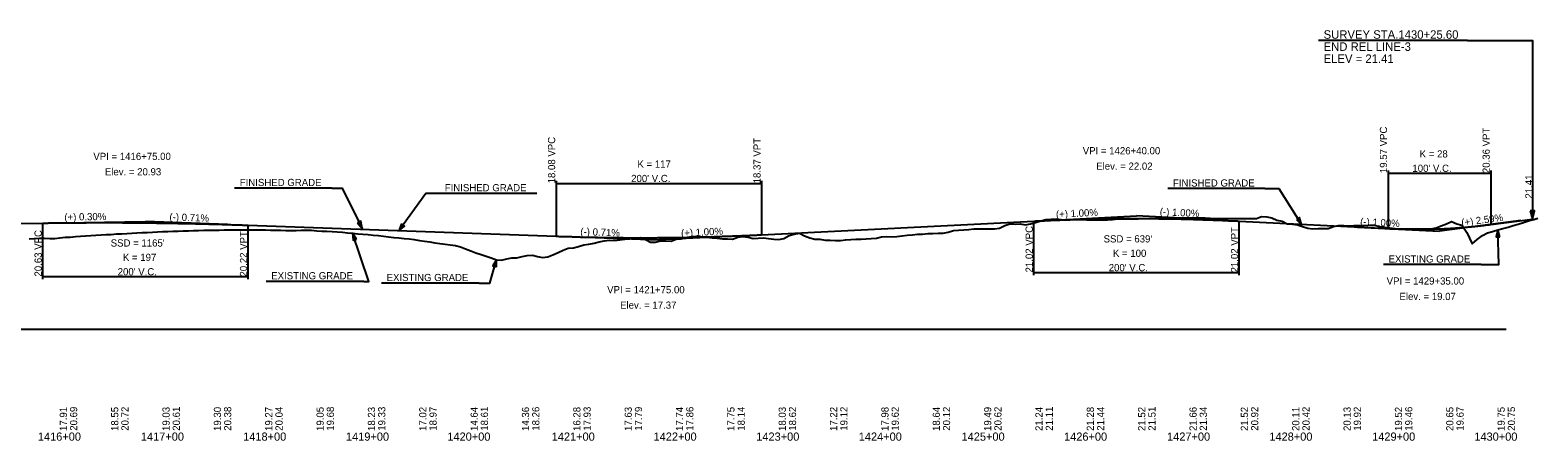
# Model space of a CAD drawing. Extents: x 2360994 to 2383826, y 330623 to 403123.
# Drawn here: x 2373088 to 2374556, y 351764 to 352164 of the extents above; entities that cross this region are included whole.
import ezdxf

# ---------------------------------------------------------------- set-up
doc = ezdxf.new("R2010")
doc.units = 0
for name, color, linetype in [('RD_DDB_GradeTX', 7, 'Continuous'), ('RD_DDB_Profile_EX', 7, 'Continuous'), ('RD_DDB_Profile_Lbl', 7, 'Continuous'), ('RD_DDB_Profile_PR', 7, 'Continuous'), ('RD_DDB_StaTX', 7, 'Continuous'), ('RD_DDB_StripGrade', 7, 'Continuous'), ('RD_DDB_VCLbl', 7, 'Continuous'), ('RD_GPK_Profile_Cell', 7, 'Continuous'), ('RD_TX_Profile', 7, 'Continuous')]:
    doc.layers.add(name, color=color, linetype=linetype)

msp = doc.modelspace()

# ---------------------------------------------------------------- linework, layer by layer
at = {"layer": 'RD_DDB_GradeTX'}
for p, q in [((2373120.6, 351976.3), (2373200.6, 351977.5)), ((2373280.5, 351974.7), (2373200.6, 351977.5)), ((2374085.7, 351979), (2374165.6, 351983)), ((2374245.5, 351979), (2374165.6, 351983)), ((2374380.7, 351972.2), (2374460.6, 351968.2)), ((2374539.9, 351978.5), (2374460.6, 351968.2)), ((2373620.6, 351962.6), (2373700.6, 351959.7)), ((2373780.5, 351963.7), (2373700.6, 351959.7))]:
    msp.add_line(p, q, dxfattribs=at)
at = {"layer": 'RD_DDB_Profile_EX'}
for points in [[(2373087.4, 351960.7), (2373092.4, 351961.1), (2373097.4, 351961.3), (2373102.4, 351961.4), (2373107.4, 351961), (2373112.4, 351961), (2373117.4, 351961.8), (2373122.4, 351962.2), (2373127.4, 351962.5), (2373132.4, 351962.9), (2373137.4, 351963.3), (2373142.4, 351963.7), (2373147.4, 351964.1), (2373152.4, 351964.4), (2373157.4, 351964.7), (2373162.4, 351964.9), (2373167.4, 351965.1), (2373172.4, 351965.5), (2373177.4, 351965.7), (2373182.4, 351966), (2373187.4, 351966.3), (2373192.4, 351966.6), (2373197.4, 351966.8), (2373202.4, 351967), (2373207.4, 351967.3), (2373212.4, 351967.5), (2373217.4, 351967.7), (2373222.4, 351967.9), (2373227.4, 351968.1), (2373232.4, 351968.3), (2373237.4, 351968.5), (2373242.4, 351968.6), (2373247.4, 351968.8), (2373252.4, 351968.9), (2373257.4, 351969.1), (2373262.4, 351969.1), (2373267.4, 351969.2), (2373272.4, 351969.3), (2373277.4, 351969.4), (2373282.4, 351969.5), (2373287.4, 351969.6), (2373292.4, 351969.6), (2373297.4, 351969.5), (2373302.4, 351969.5), (2373307.4, 351969.5), (2373312.4, 351969.4), (2373317.4, 351969.4), (2373322.4, 351969.3), (2373327.4, 351969.2), (2373332.4, 351969), (2373337.4, 351968.8), (2373342.4, 351968.8), (2373347.4, 351968.9), (2373352.4, 351969), (2373357.4, 351969.1), (2373362.4, 351969), (2373367.4, 351968.6), (2373372.4, 351968.3), (2373377.4, 351968.1), (2373382.4, 351967.9), (2373387.4, 351967.5), (2373392.4, 351967.1), (2373397.4, 351966.7), (2373402.4, 351966.2), (2373407.4, 351965.7), (2373412.4, 351965.4), (2373417.4, 351964.9)], [(2373917.4, 351962.7), (2373922.4, 351963), (2373927.4, 351962.6), (2373932.4, 351963), (2373937.4, 351963.7), (2373942.4, 351964.3), (2373947.4, 351964.7), (2373952.4, 351965.2), (2373957.4, 351965.3), (2373962.4, 351965.8), (2373967.4, 351965.8), (2373972.4, 351966.2), (2373977.4, 351966.1), (2373982.4, 351967.2), (2373987.4, 351968.9), (2373992.4, 351969.1), (2373997.4, 351969.4), (2374002.4, 351969.9), (2374007.4, 351970.4), (2374012.4, 351970.5), (2374017.4, 351970.6), (2374022.4, 351970.4), (2374027.4, 351970.3), (2374032.4, 351971), (2374037.4, 351973.7), (2374042.4, 351975.4), (2374047.4, 351975.1), (2374052.4, 351975.4), (2374057.4, 351974.5), (2374062.4, 351975.3), (2374067.4, 351976.7), (2374072.4, 351978.2), (2374077.4, 351979.6), (2374082.4, 351980), (2374087.4, 351980.1), (2374092.4, 351979.5), (2374097.4, 351979.2), (2374102.4, 351979.4), (2374107.4, 351979.4), (2374112.4, 351979.4), (2374117.4, 351979.3), (2374122.4, 351979.3), (2374127.4, 351979.2), (2374132.4, 351979.2), (2374137.4, 351979.3), (2374142.4, 351979.7), (2374147.4, 351980.1), (2374152.4, 351980.2), (2374157.4, 351980.3), (2374162.4, 351980.3), (2374167.4, 351980.3), (2374172.4, 351980.4), (2374177.4, 351980.5), (2374182.4, 351980.6), (2374187.4, 351980.8), (2374192.4, 351980.9), (2374197.4, 351981), (2374202.4, 351981.1), (2374207.4, 351981.2), (2374212.4, 351981.3), (2374217.4, 351981.3), (2374222.4, 351981.2), (2374227.4, 351981.2), (2374232.4, 351981.1), (2374237.4, 351980.9), (2374242.4, 351980.4), (2374247.4, 351980.5), (2374252.4, 351980.4), (2374257.4, 351980.4), (2374262.4, 351980.4), (2374267.4, 351980.4), (2374272.4, 351980.4), (2374277.4, 351980.5), (2374282.4, 351980.6), (2374287.4, 351982.4), (2374292.4, 351982.1), (2374297.4, 351981.3), (2374302.4, 351979), (2374307.4, 351977.9), (2374312.4, 351975.2), (2374317.4, 351975), (2374322.4, 351974.4), (2374327.4, 351972.8), (2374332.4, 351971.1), (2374337.4, 351970.6), (2374342.4, 351970.8), (2374347.4, 351970.8), (2374352.4, 351970.7), (2374357.4, 351972.7), (2374362.4, 351973.8), (2374367.4, 351973.6), (2374372.4, 351973.5), (2374377.4, 351973.6), (2374382.4, 351973.6), (2374387.4, 351973.8), (2374392.4, 351973.9), (2374397.4, 351973.9), (2374402.4, 351972.8), (2374407.4, 351972.2), (2374412.4, 351971.5), (2374417.4, 351970.9)], [(2374417.4, 351970.9), (2374422.4, 351970.4), (2374427.4, 351970.5), (2374432.4, 351970.5), (2374437.4, 351970.5), (2374442.4, 351970.4), (2374447.4, 351970.4), (2374452.4, 351970.4), (2374457.4, 351971.5), (2374462.4, 351973.4), (2374467.4, 351975.2), (2374472.4, 351977.6), (2374477.4, 351975.3), (2374482.4, 351974), (2374487.4, 351966.9), (2374492.4, 351955.9), (2374497.4, 351960.2), (2374502.4, 351963.9), (2374507.4, 351966.6), (2374512.4, 351967.9), (2374517.4, 351969.4), (2374522.4, 351970.7), (2374527.4, 351972.1), (2374532.4, 351973.6), (2374537.4, 351975.1), (2374542.4, 351976.6), (2374547.4, 351978.1), (2374552.4, 351979.4), (2374556.4, 351980.8)], [(2373417.4, 351964.9), (2373422.4, 351964.4), (2373427.4, 351963.9), (2373432.4, 351963.2), (2373437.4, 351962.6), (2373442.4, 351962.1), (2373447.4, 351961.7), (2373452.4, 351961.2), (2373457.4, 351960.6), (2373462.4, 351960), (2373467.4, 351959.2), (2373472.4, 351958.5), (2373477.4, 351957.7), (2373482.4, 351956.9), (2373487.4, 351956.1), (2373492.4, 351955.4), (2373497.4, 351954.8), (2373502.4, 351954.1), (2373507.4, 351952.9), (2373512.4, 351951), (2373517.4, 351949), (2373522.4, 351947.2), (2373527.4, 351945.5), (2373532.4, 351944), (2373537.4, 351942.3), (2373542.4, 351940.4), (2373547.4, 351940.1), (2373552.4, 351941.2), (2373557.4, 351942.2), (2373562.4, 351942.3), (2373567.4, 351943.6), (2373572.4, 351944.6), (2373577.4, 351944.7), (2373582.4, 351943.4), (2373587.4, 351942.4), (2373592.4, 351943.3), (2373597.4, 351945.2), (2373602.4, 351947.4), (2373607.4, 351949.6), (2373612.4, 351951.6), (2373617.4, 351951.8), (2373622.4, 351953.3), (2373627.4, 351954.9), (2373632.4, 351955.6), (2373637.4, 351956.6), (2373642.4, 351957.8), (2373647.4, 351958.7), (2373652.4, 351959.3), (2373657.4, 351959.1), (2373662.4, 351959.7), (2373667.4, 351960.4), (2373672.4, 351960.6), (2373677.4, 351961.3), (2373682.4, 351961.9), (2373687.4, 351960.1), (2373692.4, 351957.5), (2373697.4, 351957.6), (2373702.4, 351958.7), (2373707.4, 351958.9), (2373712.4, 351958.6), (2373717.4, 351960.3), (2373722.4, 351960.8), (2373727.4, 351962), (2373732.4, 351962.9), (2373737.4, 351963), (2373742.4, 351962.7), (2373747.4, 351962.4), (2373752.4, 351961.8), (2373757.4, 351961.3), (2373762.4, 351960.8), (2373767.4, 351960.7), (2373772.4, 351960.4), (2373777.4, 351962.3), (2373782.4, 351963.1), (2373787.4, 351962.5), (2373792.4, 351961.2), (2373797.4, 351961.4), (2373802.4, 351961.6), (2373807.4, 351961), (2373812.4, 351960.4), (2373817.4, 351960.2), (2373822.4, 351961.1), (2373827.4, 351964.1), (2373832.4, 351965.4), (2373837.4, 351966.2), (2373842.4, 351963.6), (2373847.4, 351961.6), (2373852.4, 351960.4), (2373857.4, 351960.3), (2373862.4, 351959.5), (2373867.4, 351959.4), (2373872.4, 351959), (2373877.4, 351959), (2373882.4, 351959.7), (2373887.4, 351960), (2373892.4, 351960.4), (2373897.4, 351960.4), (2373902.4, 351960.7), (2373907.4, 351961.1), (2373912.4, 351961.5), (2373917.4, 351962.7)]]:
    msp.add_lwpolyline(points, dxfattribs=at)
at = {"layer": 'RD_DDB_Profile_PR'}
for p, q in [((2372575.6, 351968.2), (2373100.6, 351976)), ((2373300.6, 351974), (2373600.6, 351963.3)), ((2373800.6, 351964.7), (2374065.6, 351978)), ((2374265.6, 351978), (2374410.6, 351970.7)), ((2374510.6, 351974.7), (2374551.2, 351979.9))]:
    msp.add_line(p, q, dxfattribs=at)
for points in [[(2373100.6, 351976), (2373104.6, 351976.1), (2373108.6, 351976.2), (2373112.6, 351976.2), (2373116.6, 351976.3), (2373120.6, 351976.3), (2373124.6, 351976.3), (2373128.6, 351976.4), (2373132.6, 351976.4), (2373136.6, 351976.4), (2373140.6, 351976.4), (2373144.6, 351976.5), (2373148.6, 351976.5), (2373152.6, 351976.5), (2373156.6, 351976.5), (2373160.6, 351976.5), (2373164.6, 351976.5), (2373168.6, 351976.5), (2373172.6, 351976.5), (2373176.6, 351976.5), (2373180.6, 351976.4), (2373184.6, 351976.4), (2373188.6, 351976.4), (2373192.6, 351976.4), (2373196.6, 351976.3), (2373200.6, 351976.3), (2373204.6, 351976.2), (2373208.6, 351976.2), (2373212.6, 351976.1), (2373216.6, 351976.1), (2373220.6, 351976), (2373224.6, 351976), (2373228.6, 351975.9), (2373232.6, 351975.8), (2373236.6, 351975.7), (2373240.6, 351975.7), (2373244.6, 351975.6), (2373248.6, 351975.5), (2373252.6, 351975.4), (2373256.6, 351975.3), (2373260.6, 351975.2), (2373264.6, 351975.1), (2373268.6, 351975), (2373272.6, 351974.9), (2373276.6, 351974.8), (2373280.6, 351974.6), (2373284.6, 351974.5), (2373288.6, 351974.4), (2373292.6, 351974.3), (2373296.6, 351974.1), (2373300.6, 351974)], [(2374065.6, 351978), (2374069.6, 351978.2), (2374073.6, 351978.3), (2374077.6, 351978.5), (2374081.6, 351978.7), (2374085.6, 351978.9), (2374089.6, 351979), (2374093.6, 351979.2), (2374097.6, 351979.3), (2374101.6, 351979.4), (2374105.6, 351979.6), (2374109.6, 351979.7), (2374113.6, 351979.8), (2374117.6, 351979.9), (2374121.6, 351980), (2374125.6, 351980.1), (2374129.6, 351980.1), (2374133.6, 351980.2), (2374137.6, 351980.3), (2374141.6, 351980.3), (2374145.6, 351980.4), (2374149.6, 351980.4), (2374153.6, 351980.4), (2374157.6, 351980.4), (2374161.6, 351980.5), (2374165.6, 351980.5), (2374169.6, 351980.5), (2374173.6, 351980.4), (2374177.6, 351980.4), (2374181.6, 351980.4), (2374185.6, 351980.4), (2374189.6, 351980.3), (2374193.6, 351980.3), (2374197.6, 351980.2), (2374201.6, 351980.1), (2374205.6, 351980.1), (2374209.6, 351980), (2374213.6, 351979.9), (2374217.6, 351979.8), (2374221.6, 351979.7), (2374225.6, 351979.6), (2374229.6, 351979.4), (2374233.6, 351979.3), (2374237.6, 351979.2), (2374241.6, 351979), (2374245.6, 351978.9), (2374249.6, 351978.7), (2374253.6, 351978.5), (2374257.6, 351978.3), (2374261.6, 351978.2), (2374265.6, 351978)], [(2374410.6, 351970.7), (2374412.6, 351970.6), (2374414.6, 351970.5), (2374416.6, 351970.4), (2374418.6, 351970.4), (2374420.6, 351970.3), (2374422.6, 351970.2), (2374424.6, 351970.2), (2374426.6, 351970.1), (2374428.6, 351970.1), (2374430.6, 351970.1), (2374432.6, 351970), (2374434.6, 351970), (2374436.6, 351970), (2374438.6, 351970), (2374440.6, 351970), (2374442.6, 351970), (2374444.6, 351970), (2374446.6, 351970.1), (2374448.6, 351970.1), (2374450.6, 351970.1), (2374452.6, 351970.2), (2374454.6, 351970.2), (2374456.6, 351970.3), (2374458.6, 351970.4), (2374460.6, 351970.5), (2374462.6, 351970.5), (2374464.6, 351970.6), (2374466.6, 351970.7), (2374468.6, 351970.8), (2374470.6, 351970.9), (2374472.6, 351971.1), (2374474.6, 351971.2), (2374476.6, 351971.3), (2374478.6, 351971.5), (2374480.6, 351971.6), (2374482.6, 351971.8), (2374484.6, 351971.9), (2374486.6, 351972.1), (2374488.6, 351972.3), (2374490.6, 351972.5), (2374492.6, 351972.6), (2374494.6, 351972.8), (2374496.6, 351973), (2374498.6, 351973.3), (2374500.6, 351973.5), (2374502.6, 351973.7), (2374504.6, 351973.9), (2374506.6, 351974.2), (2374508.6, 351974.4), (2374510.6, 351974.7)], [(2373600.6, 351963.3), (2373604.6, 351963.1), (2373608.6, 351963), (2373612.6, 351962.9), (2373616.6, 351962.8), (2373620.6, 351962.6), (2373624.6, 351962.5), (2373628.6, 351962.4), (2373632.6, 351962.4), (2373636.6, 351962.3), (2373640.6, 351962.2), (2373644.6, 351962.1), (2373648.6, 351962.1), (2373652.6, 351962), (2373656.6, 351962), (2373660.6, 351961.9), (2373664.6, 351961.9), (2373668.6, 351961.8), (2373672.6, 351961.8), (2373676.6, 351961.8), (2373680.6, 351961.8), (2373684.6, 351961.8), (2373688.6, 351961.8), (2373692.6, 351961.8), (2373696.6, 351961.8), (2373700.6, 351961.9), (2373704.6, 351961.9), (2373708.6, 351961.9), (2373712.6, 351962), (2373716.6, 351962), (2373720.6, 351962.1), (2373724.6, 351962.1), (2373728.6, 351962.2), (2373732.6, 351962.3), (2373736.6, 351962.4), (2373740.6, 351962.5), (2373744.6, 351962.6), (2373748.6, 351962.7), (2373752.6, 351962.8), (2373756.6, 351962.9), (2373760.6, 351963.1), (2373764.6, 351963.2), (2373768.6, 351963.3), (2373772.6, 351963.5), (2373776.6, 351963.6), (2373780.6, 351963.8), (2373784.6, 351964), (2373788.6, 351964.1), (2373792.6, 351964.3), (2373796.6, 351964.5), (2373800.6, 351964.7)]]:
    msp.add_spline(points, degree=3, dxfattribs=at)
at = {"layer": 'RD_DDB_VCLbl'}
for p, q in [((2374410.6, 352027.2), (2374410.6, 351970.7)), ((2374510.6, 352027.2), (2374510.6, 351974.7)), ((2373600.6, 352017.2), (2373600.6, 351963.3)), ((2373600.6, 352014.7), (2373800.6, 352014.7)), ((2373800.6, 352017.2), (2373800.6, 351964.7)), ((2374410.6, 352024.7), (2374510.6, 352024.7)), ((2373100.6, 351921.5), (2373100.6, 351976)), ((2373300.6, 351921.5), (2373300.6, 351974)), ((2374065.6, 351925.5), (2374065.6, 351978)), ((2374265.6, 351925.5), (2374265.6, 351978)), ((2374065.6, 351928), (2374265.6, 351928)), ((2373100.6, 351924), (2373300.6, 351924))]:
    msp.add_line(p, q, dxfattribs=at)
at = {"layer": 'RD_GPK_Profile_Cell'}
msp.add_line((2368825.6, 351872.9), (2374525.6, 351872.9), dxfattribs=at)
at = {"layer": 'RD_TX_Profile'}
for p, q in [((2374487.8, 352153.7), (2374342.8, 352153.7)), ((2373382, 352010.1), (2373287.5, 352010.1)), ((2373581.7, 352005), (2373487.1, 352005)), ((2374290.7, 352009.6), (2374196.1, 352009.6)), ((2374501.2, 351935.6), (2374406.1, 351935.6)), ((2373413.2, 351919.3), (2373318.1, 351919.3)), ((2373525.6, 351917.6), (2373430.5, 351917.6))]:
    msp.add_line(p, q, dxfattribs=at)
for points in [[(2374487.8, 352153.7), (2374551.1, 352153.7), (2374551.2, 351979.9)], [(2373382, 352010.1), (2373392.2, 352010.1), (2373411.8, 351970.9)], [(2373487.1, 352005), (2373473.7, 352005), (2373447.4, 351968.6)], [(2374290.7, 352009.6), (2374304.1, 352009.6), (2374326.4, 351974.8)], [(2374501.2, 351935.6), (2374518.6, 351935.6), (2374517.4, 351969.4)], [(2373413.2, 351919.3), (2373418, 351919.3), (2373402.4, 351966.2)], [(2373525.6, 351917.6), (2373536, 351917.6), (2373542.4, 351940.4)]]:
    msp.add_lwpolyline(points, dxfattribs=at)
for points in [[(2374549, 351987.9), (2374551.2, 351979.9), (2374553.3, 351987.9)], [(2373407.1, 351976.2), (2373411.8, 351970.9), (2373410.4, 351977.8)], [(2373449.9, 351975.2), (2373447.4, 351968.6), (2373452.8, 351973)], [(2374321.3, 351979.5), (2374326.4, 351974.8), (2374324.3, 351981.5)], [(2374519.4, 351962.7), (2374517.4, 351969.4), (2374515.8, 351962.6)], [(2373406.2, 351960.4), (2373402.4, 351966.2), (2373402.8, 351959.3)], [(2373542.3, 351933.4), (2373542.4, 351940.4), (2373538.8, 351934.4)]]:
    msp.add_lwpolyline(points, close=True, dxfattribs=at)

# ---------------------------------------------------------------- texts
at = {"layer": 'RD_DDB_GradeTX'}
for s, rotation, p in [('(+) 0.30%', 0.8587, (2373121.7, 351978.4)), ('(-) 0.71%', 357.9567, (2373223.9, 351978.7)), ('(+) 1.00%', 2.8624, (2374087.4, 351981.1)), ('(-) 1.00%', 357.1376, (2374188.2, 351983.8)), ('(+) 2.59%', 7.3727, (2374482.4, 351973)), ('(-) 0.71%', 357.9567, (2373624, 351964.4)), ('(+) 1.00%', 2.8624, (2373722.3, 351962.8)), ('(-) 1.00%', 357.1376, (2374383.3, 351974.1))]:
    msp.add_text(s, height=7, rotation=rotation, dxfattribs=at).set_placement(p)
at = {"layer": 'RD_DDB_Profile_Lbl'}
for s, p in [('VPI = 1416+75.00', (2373149.9, 352037.5)), ('VPI = 1426+40.00', (2374113.3, 352043)), ('Elev. = 20.93', (2373161.1, 352022.5)), ('Elev. = 22.02', (2374126.4, 352028)), ('VPI = 1421+75.00', (2373650.2, 351907.7)), ('VPI = 1429+35.00', (2374409.2, 351916.2)), ('Elev. = 17.37', (2373662.8, 351892.7)), ('Elev. = 19.07', (2374421.7, 351901.2))]:
    msp.add_text(s, height=7, dxfattribs=at).set_placement(p)
msp.add_text('21.41', height=7, rotation=90, dxfattribs=at).set_placement((2374551.2, 351999.9))
at = {"layer": 'RD_DDB_StaTX'}
for s, p in [('1416+00', (2373095.9, 351764.2)), ('1417+00', (2373196.2, 351764.2)), ('1418+00', (2373295.8, 351764.2)), ('1419+00', (2373395.9, 351764.2)), ('1420+00', (2373494.6, 351764.2)), ('1421+00', (2373596.2, 351764.2)), ('1422+00', (2373695.4, 351764.2)), ('1423+00', (2373795.4, 351764.2)), ('1424+00', (2373895.2, 351764.2)), ('1425+00', (2373995.3, 351764.2)), ('1426+00', (2374095.1, 351764.2)), ('1427+00', (2374195.4, 351764.2)), ('1428+00', (2374295, 351764.2)), ('1429+00', (2374395.1, 351764.2)), ('1430+00', (2374494.6, 351764.2))]:
    msp.add_text(s, height=8, dxfattribs=at).set_placement(p)
at = {"layer": 'RD_DDB_StripGrade'}
for s, p in [('18.08 VPC', (2373599.6, 352014.7)), ('18.37 VPT', (2373799.6, 352014.7)), ('19.57 VPC', (2374409.6, 352024.7)), ('20.36 VPT', (2374509.6, 352024.7)), ('20.63 VPC', (2373099.6, 351924)), ('21.02 VPC', (2374064.6, 351928)), ('21.02 VPT', (2374264.6, 351928)), ('20.22 VPT', (2373299.6, 351924)), ('17.91', (2373124.2, 351773.7)), ('20.69', (2373134.2, 351773.9)), ('18.55', (2373174.2, 351773.7)), ('20.72', (2373184.2, 351773.9)), ('19.03', (2373224.2, 351773.7)), ('20.61', (2373234.2, 351773.9)), ('19.30', (2373274.2, 351773.7)), ('20.38', (2373284.2, 351773.9)), ('19.27', (2373324.2, 351773.7)), ('20.04', (2373334.2, 351773.9)), ('19.05', (2373374.2, 351773.7)), ('19.68', (2373384.2, 351773.9)), ('18.23', (2373424.2, 351773.7)), ('19.33', (2373434.2, 351773.9)), ('17.02', (2373474.2, 351773.7)), ('18.97', (2373484.2, 351773.9)), ('14.64', (2373524.2, 351773.7)), ('18.61', (2373534.2, 351773.9)), ('14.36', (2373574.2, 351773.7)), ('18.26', (2373584.2, 351773.9)), ('16.28', (2373624.2, 351773.7)), ('17.93', (2373634.2, 351773.9)), ('17.63', (2373674.2, 351773.7)), ('17.79', (2373684.2, 351773.9)), ('17.74', (2373724.2, 351773.7)), ('17.86', (2373734.2, 351773.9)), ('17.75', (2373774.2, 351773.7)), ('18.14', (2373784.2, 351773.9)), ('18.03', (2373824.2, 351773.7)), ('18.62', (2373834.2, 351773.9)), ('17.22', (2373874.2, 351773.7)), ('19.12', (2373884.2, 351773.9)), ('17.98', (2373924.2, 351773.7)), ('19.62', (2373934.2, 351773.9)), ('18.64', (2373974.2, 351773.7)), ('20.12', (2373984.2, 351773.9)), ('19.49', (2374024.2, 351773.7)), ('20.62', (2374034.2, 351773.9)), ('21.24', (2374074.2, 351773.7)), ('21.11', (2374084.2, 351773.9)), ('21.28', (2374124.2, 351773.7)), ('21.44', (2374134.2, 351773.9)), ('21.52', (2374174.2, 351773.7)), ('21.51', (2374184.2, 351773.9)), ('21.66', (2374224.2, 351773.7)), ('21.34', (2374234.2, 351773.9)), ('21.52', (2374274.2, 351773.7)), ('20.92', (2374284.2, 351773.9)), ('20.11', (2374324.2, 351773.7)), ('20.42', (2374334.2, 351773.9)), ('20.13', (2374374.2, 351773.7)), ('19.92', (2374384.2, 351773.9)), ('19.52', (2374424.2, 351773.7)), ('19.46', (2374434.2, 351773.9)), ('20.65', (2374474.2, 351773.7)), ('19.67', (2374484.2, 351773.9)), ('19.75', (2374524.2, 351773.7)), ('20.75', (2374534.2, 351773.9))]:
    msp.add_text(s, height=7, rotation=90, dxfattribs=at).set_placement(p)
at = {"layer": 'RD_DDB_VCLbl'}
for s, p in [('K = 28', (2374441.4, 352039.9)), ('K = 117', (2373679.7, 352030)), ("100' V.C.", (2374434.3, 352025.9)), ("200' V.C.", (2373673.6, 352016)), ("SSD = 1165'", (2373166.8, 351953.2)), ("SSD = 639'", (2374133.6, 351957.2)), ('K = 197', (2373178.7, 351939.2)), ('K = 100', (2374142.7, 351943.2)), ("200' V.C.", (2373173.6, 351925.2)), ("200' V.C.", (2374138.6, 351929.2))]:
    msp.add_text(s, height=7, dxfattribs=at).set_placement(p)
at = {"layer": 'RD_TX_Profile'}
for s, height, p in [('SURVEY STA.1430+25.60', 8.235, (2374347.8, 352155.5)), ('END REL LINE-3', 8.235, (2374347.8, 352143.7)), ('ELEV = 21.41', 8.235, (2374347.8, 352132)), ('FINISHED GRADE', 7, (2373292.5, 352012.1)), ('FINISHED GRADE', 7, (2373492.1, 352007)), ('FINISHED GRADE', 7, (2374201.1, 352011.6)), ('EXISTING GRADE', 7, (2374411.1, 351937.6)), ('EXISTING GRADE', 7, (2373323.1, 351921.3)), ('EXISTING GRADE', 7, (2373435.5, 351919.6))]:
    msp.add_text(s, height=height, dxfattribs=at).set_placement(p)

doc.saveas('drawing.dxf')
